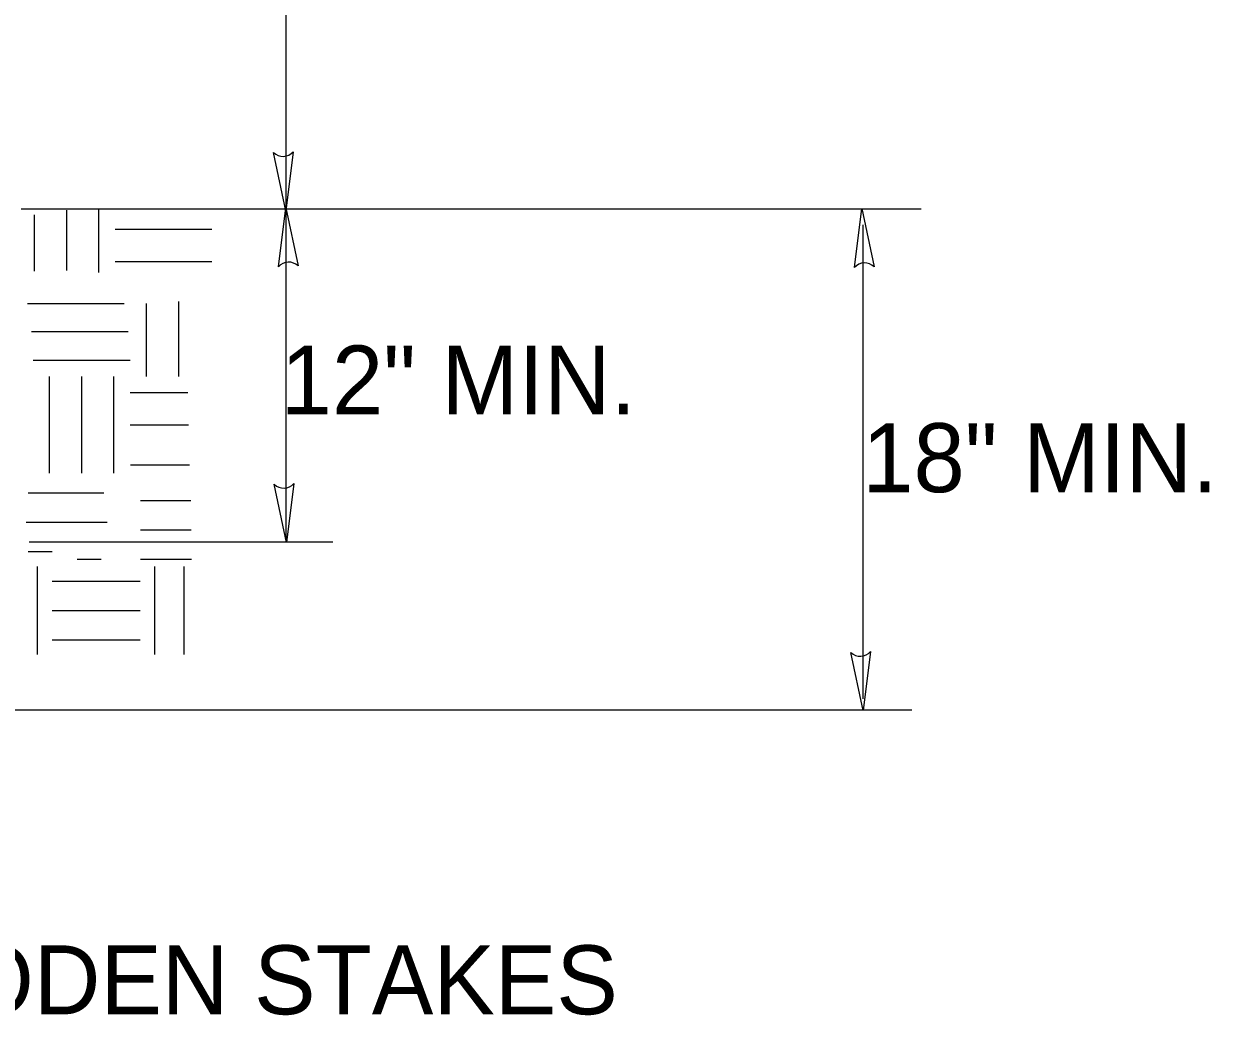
# Model space of a CAD drawing. Extents: x 0 to 2.83, y -0.06 to 1.83.
# Drawn here: x 1.0839 to 1.2344, y 0.8561 to 0.9819 of the extents above; entities that cross this region are included whole.
import ezdxf

# ---------------------------------------------------------------- set-up
doc = ezdxf.new("R2010")
doc.units = 0
for name, color, linetype in [('Edge_of_Truck_Apron', 7, 'Continuous'), ('Existing Grade', 7, 'Continuous'), ('Existing Soil', 7, 'Continuous'), ('Longitudinal Joint', 7, 'Continuous')]:
    doc.layers.add(name, color=color, linetype=linetype)

msp = doc.modelspace()

# ---------------------------------------------------------------- linework, layer by layer
at = {"layer": 'Edge_of_Truck_Apron'}
for p, q in [((1.1172228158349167, 0.9163542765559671), (1.1172228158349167, 1.1183578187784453)), ((1.1172001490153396, 0.9581797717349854), (1.1156418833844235, 0.9655646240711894)), ((1.1172001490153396, 0.9581797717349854), (1.1156418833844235, 0.9655646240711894)), ((1.1181212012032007, 0.9656708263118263), (1.1172001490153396, 0.9581797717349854)), ((1.1181212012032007, 0.9656708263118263), (1.1172001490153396, 0.9581797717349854)), ((1.1162634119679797, 0.9510619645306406), (1.1171844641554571, 0.9585530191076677)), ((1.1162634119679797, 0.9510619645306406), (1.1171844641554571, 0.9585530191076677)), ((1.1171844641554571, 0.9585530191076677), (1.1187427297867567, 0.9511681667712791)), ((1.1171844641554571, 0.9585530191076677), (1.1187427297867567, 0.9511681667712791)), ((1.189383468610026, 0.9509655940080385), (1.1903045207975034, 0.9584566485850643)), ((1.189383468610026, 0.9509655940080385), (1.1903045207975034, 0.9584566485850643)), ((1.1903045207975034, 0.9584566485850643), (1.191862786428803, 0.9510717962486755)), ((1.1903045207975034, 0.9584566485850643), (1.191862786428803, 0.9510717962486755)), ((1.1904552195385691, 0.8962530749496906), (1.1904552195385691, 0.9563939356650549)), ((1.117282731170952, 0.9160721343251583), (1.1157244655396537, 0.9234569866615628)), ((1.117282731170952, 0.9160721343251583), (1.1157244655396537, 0.9234569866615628)), ((1.1182037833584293, 0.9235631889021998), (1.117282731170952, 0.9160721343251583)), ((1.1182037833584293, 0.9235631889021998), (1.117282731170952, 0.9160721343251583)), ((1.1904658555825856, 0.8947373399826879), (1.188907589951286, 0.9021221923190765)), ((1.1904658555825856, 0.8947373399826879), (1.188907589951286, 0.9021221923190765)), ((1.1913869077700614, 0.9022283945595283), (1.1904658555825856, 0.8947373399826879)), ((1.1913869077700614, 0.9022283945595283), (1.1904658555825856, 0.8947373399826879)), ((1.1966548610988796, 0.8947995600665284), (1.0423667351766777, 0.8947995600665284))]:
    msp.add_line(p, q, dxfattribs=at)
for centre, radius, start, end in [((1.1168320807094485, 0.966772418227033), 0.0016956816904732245, 225.42043531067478, 319.4851210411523), ((1.1168320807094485, 0.966772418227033), 0.0016956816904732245, 225.42043531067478, 319.4851210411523), ((1.1175525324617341, 0.9499603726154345), 0.0016956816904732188, 45.42043531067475, 139.48512104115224), ((1.1175525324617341, 0.9499603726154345), 0.0016956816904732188, 45.42043531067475, 139.48512104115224), ((1.1906725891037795, 0.9498640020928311), 0.0016956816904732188, 45.42043531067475, 139.48512104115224), ((1.1906725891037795, 0.9498640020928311), 0.0016956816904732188, 45.42043531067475, 139.48512104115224), ((1.116914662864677, 0.9246647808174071), 0.0016956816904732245, 225.42043531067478, 319.4851210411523), ((1.116914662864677, 0.9246647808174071), 0.0016956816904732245, 225.42043531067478, 319.4851210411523), ((1.19009778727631, 0.9033299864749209), 0.0016956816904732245, 225.42043531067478, 319.4851210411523), ((1.19009778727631, 0.9033299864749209), 0.0016956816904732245, 225.42043531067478, 319.4851210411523)]:
    msp.add_arc(centre, radius, start, end, dxfattribs=at)
at = {"layer": 'Existing Grade'}
msp.add_line((1.083617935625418, 0.958423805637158), (1.1978507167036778, 0.958423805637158), dxfattribs=at)
at = {"layer": 'Existing Soil'}
for p, q in [((1.0852857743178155, 0.9505075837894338), (1.0852857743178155, 0.9576682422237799)), ((1.0852857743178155, 0.9505075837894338), (1.0852857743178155, 0.9576682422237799)), ((1.0893804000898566, 0.9505838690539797), (1.0893804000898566, 0.9582409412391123)), ((1.0893804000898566, 0.9505838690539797), (1.0893804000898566, 0.9582409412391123)), ((1.0934750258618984, 0.9503550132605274), (1.0934750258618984, 0.9582728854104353)), ((1.0934750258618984, 0.9503550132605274), (1.0934750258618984, 0.9582728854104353)), ((1.095522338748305, 0.9558495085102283), (1.1078062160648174, 0.9558495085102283)), ((1.095522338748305, 0.9558495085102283), (1.1078062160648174, 0.9558495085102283)), ((1.095522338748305, 0.9517548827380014), (1.1078062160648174, 0.9517548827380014)), ((1.095522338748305, 0.9517548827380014), (1.1078062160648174, 0.9517548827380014)), ((1.1035709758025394, 0.9466678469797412), (1.1035709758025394, 0.9371405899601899)), ((1.1035709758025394, 0.9466678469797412), (1.1035709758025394, 0.9371405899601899)), ((1.096693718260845, 0.9463749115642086), (1.0844098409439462, 0.9463749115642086)), ((1.096693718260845, 0.9463749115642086), (1.0844098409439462, 0.9463749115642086)), ((1.0994763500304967, 0.946423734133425), (1.0994763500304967, 0.9371405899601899)), ((1.0994763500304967, 0.946423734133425), (1.0994763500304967, 0.9371405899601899)), ((1.0971849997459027, 0.942810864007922), (1.0849011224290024, 0.942810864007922)), ((1.0971849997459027, 0.942810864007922), (1.0849011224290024, 0.942810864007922)), ((1.0974290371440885, 0.9391879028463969), (1.0851451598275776, 0.9391879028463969)), ((1.0974290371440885, 0.9391879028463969), (1.0851451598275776, 0.9391879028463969)), ((1.0871924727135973, 0.9248567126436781), (1.0871924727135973, 0.9371405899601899)), ((1.0871924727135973, 0.9248567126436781), (1.0871924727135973, 0.9371405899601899)), ((1.0912870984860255, 0.9248567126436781), (1.0912870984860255, 0.9371405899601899)), ((1.0912870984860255, 0.9248567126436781), (1.0912870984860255, 0.9371405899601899)), ((1.0953817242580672, 0.9248567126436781), (1.0953817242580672, 0.9371405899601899)), ((1.0953817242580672, 0.9248567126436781), (1.0953817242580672, 0.9371405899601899)), ((1.0974290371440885, 0.935093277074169), (1.1047600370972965, 0.935093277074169)), ((1.0974290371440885, 0.935093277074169), (1.1047600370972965, 0.935093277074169)), ((1.0974290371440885, 0.930998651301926), (1.1048239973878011, 0.930998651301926)), ((1.0974290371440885, 0.930998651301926), (1.1048239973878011, 0.930998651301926)), ((1.0974934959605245, 0.925936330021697), (1.1049524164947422, 0.925936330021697)), ((1.0974934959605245, 0.925936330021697), (1.1049524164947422, 0.925936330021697)), ((1.0940794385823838, 0.9223292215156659), (1.0844725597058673, 0.9223292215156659)), ((1.0940794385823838, 0.9223292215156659), (1.0844725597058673, 0.9223292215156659)), ((1.1051250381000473, 0.921361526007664), (1.0987547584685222, 0.921361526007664)), ((1.1051250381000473, 0.921361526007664), (1.0987547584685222, 0.921361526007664)), ((1.1051674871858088, 0.9176391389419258), (1.0987547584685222, 0.9176391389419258)), ((1.1051674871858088, 0.9176391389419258), (1.0987547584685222, 0.9176391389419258)), ((1.0875231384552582, 0.914884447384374), (1.0844725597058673, 0.914884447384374)), ((1.0875231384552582, 0.914884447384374), (1.0844725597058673, 0.914884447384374)), ((1.0937695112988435, 0.9139238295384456), (1.0907189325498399, 0.9139238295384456)), ((1.0937695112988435, 0.9139238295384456), (1.0907189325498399, 0.9139238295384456)), ((1.1052099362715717, 0.913916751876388), (1.0987547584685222, 0.913916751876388)), ((1.1052099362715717, 0.913916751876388), (1.0987547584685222, 0.913916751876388)), ((1.0856619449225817, 0.9018560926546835), (1.0856619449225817, 0.9130232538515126)), ((1.0856619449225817, 0.9018560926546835), (1.0856619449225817, 0.9130232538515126)), ((1.1005514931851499, 0.9018560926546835), (1.1005514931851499, 0.9130232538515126)), ((1.1005514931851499, 0.9018560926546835), (1.1005514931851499, 0.9130232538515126)), ((1.1042738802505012, 0.9018560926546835), (1.1042738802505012, 0.9130232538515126)), ((1.1042738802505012, 0.9018560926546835), (1.1042738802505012, 0.9130232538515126)), ((1.0875231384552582, 0.9111620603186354), (1.098690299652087, 0.9111620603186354)), ((1.0875231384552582, 0.9111620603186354), (1.098690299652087, 0.9111620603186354)), ((1.0875231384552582, 0.9074396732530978), (1.098690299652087, 0.9074396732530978)), ((1.0875231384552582, 0.9074396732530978), (1.098690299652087, 0.9074396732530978)), ((1.0875231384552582, 0.9037172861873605), (1.098690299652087, 0.9037172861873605)), ((1.0875231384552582, 0.9037172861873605), (1.098690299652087, 0.9037172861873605))]:
    msp.add_line(p, q, dxfattribs=at)
at = {"layer": 'Longitudinal Joint'}
for p, q in [((1.1172228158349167, 0.9163542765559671), (1.1172228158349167, 1.1183578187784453)), ((1.083617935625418, 0.958423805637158), (1.1978507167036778, 0.958423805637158)), ((1.1904552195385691, 0.8962530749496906), (1.1904552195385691, 0.9563939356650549)), ((1.0945200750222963, 0.9186068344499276), (1.0842310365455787, 0.9186068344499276)), ((1.0945200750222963, 0.9186068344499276), (1.0842310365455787, 0.9186068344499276)), ((1.123141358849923, 0.9161082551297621), (1.0846148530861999, 0.9161082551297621)), ((1.123141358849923, 0.9161082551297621), (1.0846148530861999, 0.9161082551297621)), ((1.1966548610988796, 0.8947995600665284), (1.0423667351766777, 0.8947995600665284))]:
    msp.add_line(p, q, dxfattribs=at)

# ---------------------------------------------------------------- texts
at = {"layer": 'Edge_of_Truck_Apron'}
for s, p in [('12" MIN.', (1.1165375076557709, 0.9323220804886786)), ('18" MIN.', (1.1903508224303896, 0.9224602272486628)), ('TWO WOODEN STAKES ', (1.0254151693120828, 0.8561972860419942))]:
    msp.add_text(s, height=0.008749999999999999, dxfattribs=at).set_placement(p)

doc.saveas('drawing.dxf')
